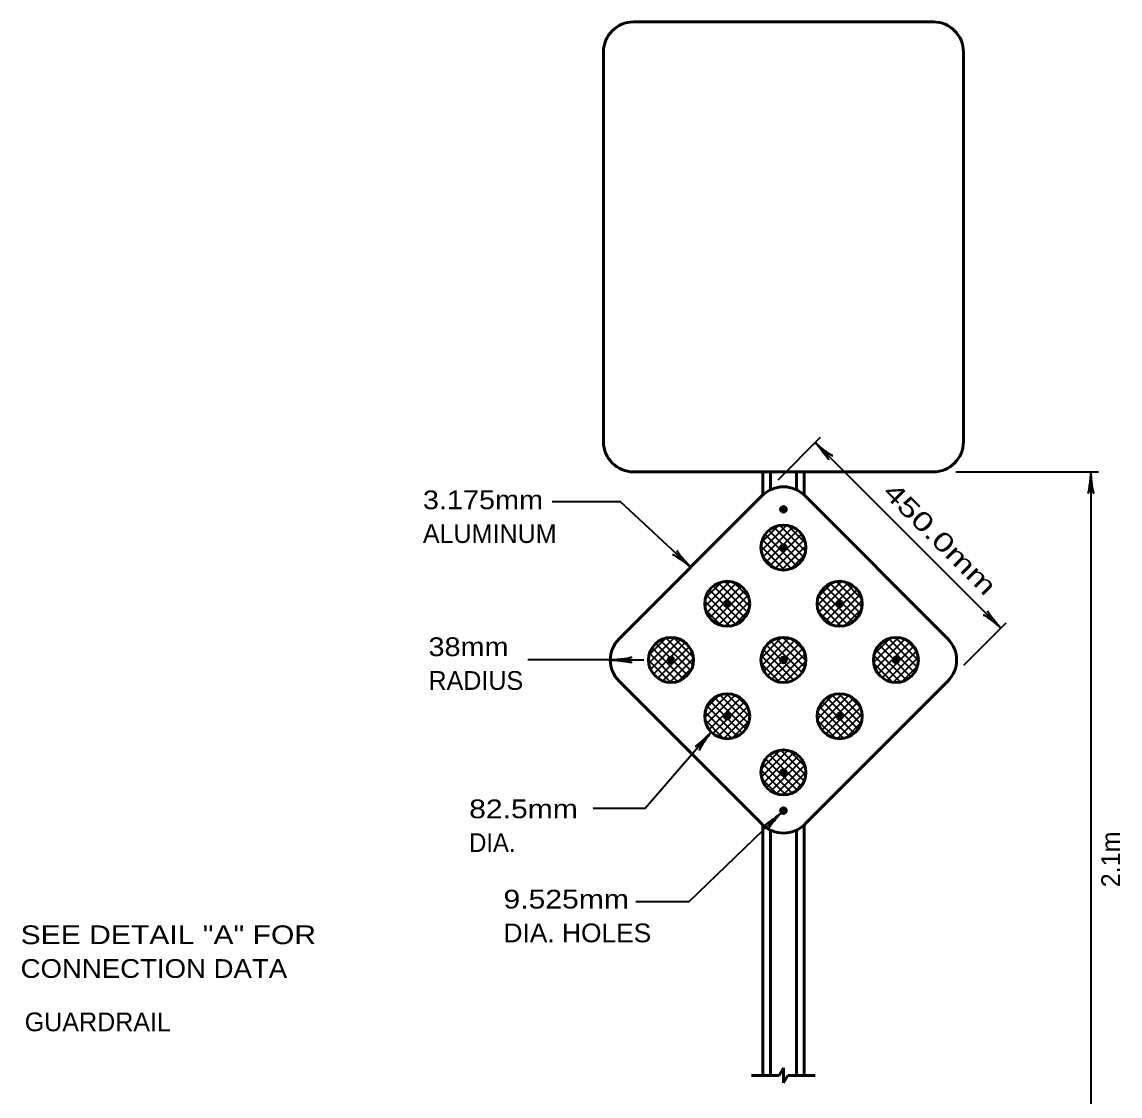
# Model space of a CAD drawing. Extents: x -89 to 766, y -60 to 484.
# Drawn here: x 215.3 to 391.1, y 59 to 230.9 of the extents above; entities that cross this region are included whole.
import ezdxf

# ---------------------------------------------------------------- set-up
doc = ezdxf.new("R2010")
doc.units = 0
doc.header["$LTSCALE"] = 1.1
doc.layers.add('1', color=7, linetype='Continuous', lineweight=35)

msp = doc.modelspace()

# ---------------------------------------------------------------- hatches: boundary and pattern name
at = {"layer": '1'}
for points in [[(337.647, 152.853, 1), (336.747, 152.853, 1)], [(337.647, 146.742, 1), (336.747, 146.742, 1)], [(328.647, 137.742, 1), (327.747, 137.742, 1)], [(346.647, 137.742, 1), (345.747, 137.742, 1)], [(319.647, 128.742, 1), (318.747, 128.742, 1)], [(337.647, 128.742, 1), (336.747, 128.742, 1)], [(355.647, 128.742, 1), (354.747, 128.742, 1)], [(328.647, 119.742, 1), (327.747, 119.742, 1)], [(346.647, 119.742, 1), (345.747, 119.742, 1)], [(337.647, 110.742, 1), (336.747, 110.742, 1)], [(337.647, 104.632, 1), (336.747, 104.632, 1)]]:
    msp.add_hatch(color=256, dxfattribs=at).paths.add_polyline_path(points)

# ---------------------------------------------------------------- linework, layer by layer
at = {"layer": '1', "lineweight": 53}
for p, q in [((313.197, 230.853), (361.197, 230.853)), ((308.397, 163.653), (308.397, 226.053)), ((365.997, 226.053), (365.997, 163.653)), ((361.197, 158.853), (313.197, 158.853)), ((333.897, 155.141), (333.897, 158.853)), ((335.097, 155.969), (335.097, 158.853)), ((339.297, 155.969), (339.297, 158.853)), ((340.497, 155.141), (340.497, 158.853)), ((310.892, 132.136), (333.803, 155.047)), ((340.591, 155.047), (363.501, 132.136)), ((333.803, 102.438), (310.892, 125.348)), ((363.501, 125.348), (340.591, 102.438)), ((333.897, 62.253), (333.897, 102.344)), ((340.497, 62.253), (340.497, 102.344)), ((335.097, 62.253), (335.097, 101.516)), ((339.297, 62.253), (339.297, 101.516)), ((337.197, 63.453), (336.504, 62.253)), ((337.197, 63.453), (337.197, 61.053)), ((332.097, 62.253), (336.504, 62.253)), ((337.197, 61.053), (337.889, 62.253)), ((337.889, 62.253), (342.297, 62.253))]:
    msp.add_line(p, q, dxfattribs=at)
at = {"layer": '1'}
for p, q in [((336.348, 157.592), (343.136, 164.381)), ((342.288, 163.532), (371.986, 133.833)), ((364.797, 158.853), (387.597, 158.853)), ((386.397, 158.853), (386.397, 30.453)), ((333.639, 146.231), (337.711, 150.302)), ((333.701, 147.565), (336.376, 150.24)), ((333.929, 145.247), (338.695, 150.013)), ((334.415, 144.461), (339.475, 149.521)), ((339.927, 144.409), (334.86, 149.476)), ((340.432, 145.177), (335.632, 149.976)), ((340.74, 146.142), (336.597, 150.285)), ((340.721, 147.433), (337.886, 150.269)), ((338.425, 143.365), (333.82, 147.97)), ((339.261, 143.803), (334.254, 148.809)), ((335.071, 143.843), (340.093, 148.866)), ((335.894, 143.394), (340.544, 148.044)), ((337.363, 143.154), (333.605, 146.913)), ((336.931, 143.158), (340.778, 147.005)), ((335.819, 143.426), (333.867, 145.378)), ((338.404, 143.358), (340.591, 145.546)), ((324.627, 137.299), (328.636, 141.309)), ((324.728, 138.673), (327.275, 141.22)), ((324.902, 136.302), (329.636, 141.036)), ((331.504, 136.343), (326.792, 141.055)), ((331.767, 137.352), (327.803, 141.317)), ((331.656, 138.736), (329.195, 141.197)), ((342.615, 137.436), (346.499, 141.321)), ((342.782, 138.876), (345.053, 141.147)), ((342.857, 136.406), (347.529, 141.077)), ((343.317, 135.593), (348.345, 140.62)), ((349.459, 136.239), (344.691, 141.007)), ((349.75, 137.221), (345.672, 141.299)), ((349.697, 138.547), (347.002, 141.242)), ((329.598, 134.431), (324.888, 139.14)), ((330.403, 134.899), (325.359, 139.943)), ((325.378, 135.505), (330.429, 140.556)), ((331.035, 135.539), (325.993, 140.581)), ((326.026, 134.88), (331.058, 139.912)), ((326.837, 134.419), (331.522, 139.104)), ((347.493, 134.387), (342.846, 139.034)), ((348.314, 134.839), (343.293, 139.859)), ((348.968, 135.458), (343.906, 140.519)), ((343.943, 134.946), (348.995, 139.998)), ((344.732, 134.463), (349.482, 139.212)), ((328.589, 134.167), (324.627, 138.129)), ((327.858, 134.167), (331.773, 138.082)), ((346.45, 134.157), (342.613, 137.994)), ((345.725, 134.182), (349.763, 138.22)), ((327.189, 134.294), (324.747, 136.736)), ((329.284, 134.32), (331.623, 136.659)), ((344.973, 134.361), (342.822, 136.513)), ((347.066, 134.25), (349.68, 136.864)), ((366.047, 127.894), (372.835, 134.682)), ((315.64, 128.226), (319.716, 132.302)), ((315.699, 129.558), (318.383, 132.242)), ((315.931, 127.244), (320.699, 132.012)), ((322.361, 127.032), (317.49, 131.903)), ((322.706, 127.959), (318.417, 132.249)), ((322.766, 129.172), (319.629, 132.309)), ((333.617, 129.036), (336.904, 132.323)), ((333.709, 127.855), (338.078, 132.224)), ((334.078, 126.951), (338.984, 131.857)), ((340.6, 127.578), (336.037, 132.141)), ((340.794, 128.657), (337.117, 132.334)), ((340.452, 130.272), (338.721, 132.003)), ((351.619, 128.341), (355.591, 132.313)), ((351.744, 129.738), (354.207, 132.201)), ((351.886, 127.334), (356.601, 132.049)), ((358.605, 127.594), (354.052, 132.147)), ((358.795, 128.677), (355.136, 132.335)), ((358.428, 130.317), (356.765, 131.98)), ((321.131, 125.716), (316.168, 130.679)), ((316.418, 126.458), (321.478, 131.518)), ((321.829, 126.292), (316.749, 131.371)), ((317.074, 125.841), (322.095, 130.862)), ((338.821, 125.539), (333.99, 130.37)), ((339.578, 126.055), (334.505, 131.128)), ((334.63, 126.23), (339.709, 131.309)), ((340.175, 126.731), (335.186, 131.719)), ((335.341, 125.668), (340.274, 130.601)), ((356.835, 125.546), (351.997, 130.383)), ((352.358, 126.534), (357.401, 131.577)), ((357.589, 126.064), (352.514, 131.14)), ((352.999, 125.902), (358.038, 130.94)), ((358.183, 126.743), (353.198, 131.728)), ((353.803, 125.433), (358.509, 130.139)), ((309.486, 128.742), (296.286, 128.742)), ((309.486, 128.742), (314.872, 128.744)), ((319.153, 125.149), (315.605, 128.697)), ((320.262, 125.313), (315.762, 129.812)), ((317.898, 125.393), (322.546, 130.04)), ((318.936, 125.158), (322.778, 129)), ((337.873, 125.215), (333.666, 129.422)), ((336.229, 125.284), (340.661, 129.715)), ((337.373, 125.155), (340.792, 128.573)), ((355.89, 125.218), (351.67, 129.438)), ((354.814, 125.172), (358.769, 129.127)), ((317.391, 125.638), (316.078, 126.951)), ((320.412, 125.361), (322.589, 127.538)), ((336.62, 125.194), (333.652, 128.162)), ((339.362, 125.871), (340.062, 126.571)), ((354.644, 125.191), (351.648, 128.188)), ((356.213, 125.297), (358.641, 127.726)), ((324.612, 119.516), (328.423, 123.327)), ((324.837, 118.468), (329.469, 123.1)), ((324.838, 121.014), (326.925, 123.102)), ((331.598, 118.569), (327.029, 123.138)), ((331.794, 119.646), (328.106, 123.334)), ((342.62, 119.335), (346.598, 123.312)), ((342.741, 120.728), (345.218, 123.205)), ((342.888, 118.329), (347.606, 123.048)), ((349.581, 118.518), (344.978, 123.121)), ((349.792, 119.58), (346.041, 123.33)), ((349.511, 121.133), (347.591, 123.053)), ((329.813, 116.535), (324.986, 121.363)), ((325.284, 117.642), (330.298, 122.656)), ((330.572, 117.049), (325.499, 122.122)), ((325.898, 116.983), (330.96, 122.045)), ((331.17, 117.724), (326.179, 122.715)), ((326.674, 116.487), (331.454, 121.267)), ((331.465, 121.247), (329.702, 123.011)), ((347.767, 116.513), (342.961, 121.32)), ((343.361, 117.53), (348.406, 122.574)), ((348.536, 117.017), (343.47, 122.084)), ((344.003, 116.898), (349.041, 121.936)), ((349.144, 117.682), (344.14, 122.686)), ((328.863, 116.213), (324.663, 120.412)), ((327.651, 116.191), (331.752, 120.292)), ((346.804, 116.203), (342.65, 120.358)), ((344.808, 116.431), (349.511, 121.134)), ((345.821, 116.171), (349.77, 120.12)), ((327.607, 116.196), (324.655, 119.148)), ((328.963, 116.23), (331.712, 118.979)), ((345.53, 116.205), (342.67, 119.065)), ((347.223, 116.3), (349.639, 118.716)), ((333.643, 111.293), (336.644, 114.294)), ((333.673, 110.05), (337.89, 114.268)), ((340.764, 110.323), (336.772, 114.315)), ((334, 109.105), (338.836, 113.94)), ((339.383, 107.885), (334.344, 112.924)), ((334.518, 108.35), (339.594, 113.426)), ((340.02, 108.521), (334.974, 113.567)), ((335.196, 107.755), (340.184, 112.743)), ((340.494, 109.32), (335.768, 114.046)), ((340.665, 111.694), (338.152, 114.207)), ((337.561, 107.162), (333.624, 111.099)), ((338.575, 107.42), (333.879, 112.117)), ((336.046, 107.332), (340.602, 111.888)), ((337.135, 107.148), (340.792, 110.806)), ((336.144, 107.306), (333.763, 109.687)), ((338.777, 107.518), (340.428, 109.168))]:
    msp.add_line(p, q, dxfattribs=at)
for points in [[(322.348, 143.592), (311.099, 154.03), (300.158, 154.03)], [(325.651, 117.197), (315.061, 104.968), (306.76, 104.968)], [(336.879, 104.314), (322.04, 90.061), (313.551, 90.061)]]:
    msp.add_lwpolyline(points, dxfattribs=at)
at = {"layer": '1', "lineweight": 53}
for centre, radius in [((337.197, 152.853), 0.45), ((337.197, 146.742), 3.6), ((337.197, 146.742), 0.45), ((328.197, 137.742), 3.6), ((346.197, 137.742), 3.6), ((328.197, 137.742), 0.45), ((346.197, 137.742), 0.45), ((319.197, 128.742), 3.6), ((337.197, 128.742), 3.6), ((355.197, 128.742), 3.6), ((319.197, 128.742), 0.45), ((337.197, 128.742), 0.45), ((355.197, 128.742), 0.45), ((328.197, 119.742), 3.6), ((346.197, 119.742), 3.6), ((328.197, 119.742), 0.45), ((346.197, 119.742), 0.45), ((337.197, 110.742), 3.6), ((337.197, 110.742), 0.45), ((337.197, 104.632), 0.45)]:
    msp.add_circle(centre, radius, dxfattribs=at)
for centre, start, end in [((313.197, 226.053), 90, 180), ((361.197, 226.053), 0, 90), ((313.197, 163.653), 180, 270), ((361.197, 163.653), 270, 0), ((337.197, 151.653), 45.00033, 135), ((314.286, 128.742), 135, 225), ((360.107, 128.742), 315, 44.99948), ((337.197, 105.832), 225, 315)]:
    msp.add_arc(centre, 4.8, start, end, dxfattribs=at)
at = {"layer": '1', "lineweight": 40}
for centre, major_axis, ratio, start_param, end_param in [((343.059, 162.402), (-1.341, 1.639), 0.07063, 3.1407148, 5.41811), ((343.059, 162.402), (-1.341, 1.639), 0.07063, 3.1407148, 5.41811), ((343.448, 162.84), (-1.648, 1.383), 0.122415, 0.8963533, 3.1415927), ((343.448, 162.84), (-1.648, 1.383), 0.122415, 0.8963533, 3.1415927), ((386.143, 157.508), (0.211, 2.108), 0.07063, 3.1407148, 5.41811), ((386.728, 157.543), (-0.187, 2.143), 0.122415, 0.8963533, 3.1415927), ((321.535, 144.692), (-1.402, 1.588), 0.07063, 6.2823074, 8.5597026), ((321.535, 144.692), (-1.402, 1.588), 0.07063, 6.2823074, 8.5597026), ((321.162, 144.239), (1.698, -1.32), 0.122415, 0.8963533, 3.1415927), ((321.162, 144.239), (1.698, -1.32), 0.122415, 0.8963533, 3.1415927), ((370.826, 134.525), (1.648, -1.383), 0.122415, 0.8963533, 3.1415927), ((370.826, 134.525), (1.648, -1.383), 0.122415, 0.8963533, 3.1415927), ((371.215, 134.964), (1.341, -1.639), 0.07063, 3.1407148, 5.41811), ((371.215, 134.964), (1.341, -1.639), 0.07063, 3.1407148, 5.41811), ((310.831, 128.489), (-2.108, 0.21), 0.07063, 3.1407148, 5.41811), ((310.796, 129.074), (-2.143, -0.188), 0.122415, 0.8963533, 3.1415927), ((324.579, 116.347), (-1.539, -1.455), 0.07063, 6.2823074, 8.5597026), ((324.579, 116.347), (-1.539, -1.455), 0.07063, 6.2823074, 8.5597026), ((325.044, 115.99), (1.261, 1.742), 0.122415, 0.8963533, 3.1415927), ((325.044, 115.99), (1.261, 1.742), 0.122415, 0.8963533, 3.1415927), ((335.733, 103.565), (-1.666, -1.308), 0.07063, 6.2823074, 8.5597026), ((335.733, 103.565), (-1.666, -1.308), 0.07063, 6.2823074, 8.5597026), ((336.164, 103.168), (1.416, 1.62), 0.122415, 0.8963533, 3.1415927), ((336.164, 103.168), (1.416, 1.62), 0.122415, 0.8963533, 3.1415927)]:
    msp.add_ellipse(centre, major_axis=major_axis, ratio=ratio, start_param=start_param, end_param=end_param, dxfattribs=at)

# ---------------------------------------------------------------- texts
at = {"layer": '1'}
for s, width, p in [('3.175mm', 1.15, (279.491, 152.873)), ('38mm', 1.15, (280.384, 129.36)), ('82.5mm', 1.2, (286.897, 103.415)), ('DIA.', 0.95, (286.897, 98.014)), ('9.525mm', 1.2, (292.391, 88.963)), ('SEE DETAIL "A" FOR', 1.2, (215.106, 83.261)), ('DIA. HOLES', 1.05, (292.391, 83.563)), ('CONNECTION DATA', 1.1, (215.106, 77.861))]:
    msp.add_text(s, height=3, dxfattribs=dict(at, width=width)).set_placement(p)
at = {"layer": '1', "width": 1.4}
msp.add_text('450.0mm', height=3, rotation=315, dxfattribs=at).set_placement((352.912, 155.362))
at = {"layer": '1'}
for s, p in [('ALUMINUM', (279.491, 147.473)), ('RADIUS', (280.384, 123.96)), ('GUARDRAIL', (215.763, 69.322))]:
    msp.add_text(s, height=3, dxfattribs=at).set_placement(p)
msp.add_text('2.1m', height=3, rotation=90, dxfattribs=at).set_placement((391.063, 92.372))

doc.saveas('drawing.dxf')
